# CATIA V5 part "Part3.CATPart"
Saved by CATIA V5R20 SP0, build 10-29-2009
Part number: Part3
Bounding box of the stored display mesh (mm): x -250 to -79.373, y -20 to 20, z 300 to 320
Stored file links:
  C:\Users\Orange\Desktop\Assembly Design-5\Part3.CATPart
  C:\Users\Orange\Desktop\Assembly Design-5\Product1.CATProduct
  C:\Users\Orange\Desktop\Assembly Design-5\Part2.CATPart
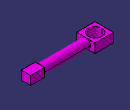
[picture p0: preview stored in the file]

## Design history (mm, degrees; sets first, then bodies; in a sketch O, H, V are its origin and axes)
Body1 (main body)
  DatumSurface1
  DatumCurve1
  Sketch1 on face of DatumSurface1, origin (0, 0, 300), H (1, 0, 0), V (0, 1, 0)
    line L1 (-110, -10) -> (-110, 10)
    arc A1 centre (0.006, 0) radius 80.006 from (-79.3726, 10) to (-79.3726, -10) ccw
    line L2 (-110, -10) -> (-79.3726, -10)
    line L3 (-110, 10) -> (-79.3726, 10)
    vertical: L1 V
    horizontal: L2 H, L3 H
  Pad1: profile Sketch1, direction (0, 0, 1), length 19
  DatumSurface2
  Sketch2 on face of Pad1 from Sketch1.L1, origin (-110, 0, 0), H (0, -1, 0), V (0, 0, 1)
    circle A1 centre (0, 310) radius 10
    point P1 (0, 310)
    point P2 (0, 320)
    coincidence: P1 V, A1 P2, P2 V
  Pad2: profile Sketch2, direction (-1, 0, 0), length 100
  Sketch3 on face of DatumSurface2, origin (0, 0, 350), H (1, 0, 0), V (0, 1, 0)
  DatumSurface3
  Plane1: type Offset, RefPlane DatumSurface3, Offset 30
  DatumCurve2
  Sketch4 on Plane1, origin (0, 0, 320), H (1, 0, 0), V (0, -1, 0)
    line L1 (-210, 20) -> (-250, 20)
    line L2 (-250, 20) -> (-250, -20)
    line L3 (-250, -20) -> (-210, -20)
    line L4 (-210, -20) -> (-210, 20)
    circle A1 centre (-229.994, 0) radius 15
    horizontal: L1 H, L3 H
    vertical: L2 V, L4 V
  Pad3: profile Sketch4, direction (0, 0, -1), length 20
  DatumCurve3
